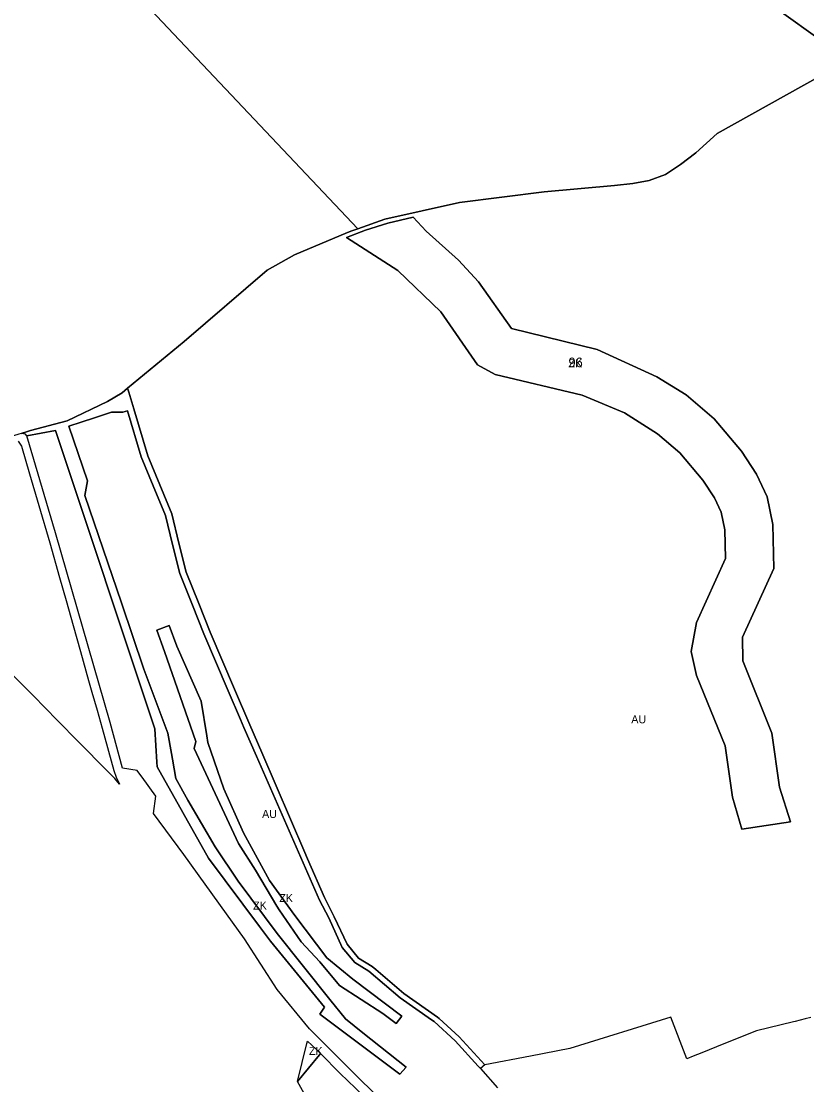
# Model space of a CAD drawing. Extents: x -535894 to -532834, y -1165802 to -1163647.
# Drawn here: x -535328 to -534838, y -1165127 to -1164462 of the extents above; entities that cross this region are included whole.
import ezdxf

# ---------------------------------------------------------------- set-up
doc = ezdxf.new("R2010")
doc.units = 0
for name, color, linetype in [('Vrstva 16', 7, 'Continuous'), ('Vrstva 17', 7, 'Continuous'), ('Vrstva 19', 7, 'Continuous'), ('Vrstva 22', 7, 'Continuous'), ('Vrstva 28', 7, 'Continuous'), ('Vrstva 61', 7, 'Continuous')]:
    doc.layers.add(name, color=color, linetype=linetype)

msp = doc.modelspace()

# ---------------------------------------------------------------- linework, layer by layer
at = {"layer": 'Vrstva 16'}
for points in [[(-535138.71, -1165009.74), (-535132.68, -1165021.61), (-535124.68, -1165038.88), (-535117.6, -1165047.48), (-535109.11, -1165052.7), (-535106.82, -1165054.65), (-535089.33, -1165069.61), (-535068.17, -1165084.42), (-535067.25, -1165085.28), (-535054.81, -1165096.75), (-535038.78, -1165114.13), (-535041.39, -1165116.45), (-535042.82, -1165114.91), (-535057.29, -1165099.23), (-535070.36, -1165087.15), (-535071.93, -1165086.06), (-535091.48, -1165072.37), (-535111.17, -1165055.54), (-535119.93, -1165050.16), (-535127.67, -1165040.76), (-535136.18, -1165022.4), (-535141.82, -1165011.33), (-535181.28, -1164921.44), (-535189.08, -1164903.47), (-535191.25, -1164898.41), (-535198.89, -1164880.55), (-535214.13, -1164844.92), (-535221.25, -1164827.04), (-535229.1, -1164807.35), (-535233.62, -1164789.13), (-535238.13, -1164771.01), (-535245.75, -1164752.59), (-535253.23, -1164734.48), (-535261.71, -1164705.66), (-535264.79, -1164706.6), (-535271.8, -1164706.52), (-535282.32, -1164710.05), (-535290.79, -1164712.78), (-535298.39, -1164715.22), (-535286.78, -1164749.373), (-535288.44, -1164758.51), (-535265.51, -1164825.67), (-535251.57, -1164867.01), (-535236.56, -1164907.02), (-535234.352, -1164919.797), (-535233.753, -1164923.265), (-535231.67, -1164935.322), (-535224.17, -1164948.96), (-535207, -1164978.01), (-535192.6, -1164999.49), (-535168.36, -1165032.09), (-535135.5, -1165073.361), (-535125.69, -1165085.45), (-535114.8, -1165094.19), (-535087.801, -1165115.542), (-535091.8, -1165120.03), (-535141.75, -1165082.45), (-535138.85, -1165078.22), (-535172.47, -1165036.89), (-535179.28, -1165027.8), (-535211.27, -1164985.05), (-535243.3, -1164928.03), (-535243.48, -1164925.188), (-535244.804, -1164904.255), (-535306.74, -1164717.91), (-535324.72, -1164721.28), (-535325.538, -1164720.285), (-535327.926, -1164719.801), (-535325.391, -1164719.016), (-535322.24, -1164718.04), (-535299.42, -1164711.94), (-535274.36, -1164699.8), (-535265.14, -1164694.54), (-535261.677, -1164691.669), (-535260.94, -1164694.17), (-535257.9, -1164704.48), (-535249.16, -1164733.82), (-535241.65, -1164751.91), (-535234.09, -1164770.13), (-535229.64, -1164788.31), (-535225.1, -1164806.57), (-535217.32, -1164826.11), (-535210.21, -1164843.9), (-535194.99, -1164879.49), (-535185.4, -1164901.91), (-535177.9, -1164919.08), (-535151, -1164981.54), (-535149.32, -1164985.4)], [(-535211.657, -1164912.919), (-535201.69, -1164941.88), (-535189.32, -1164969.17), (-535173.15, -1164998.99), (-535157.24, -1165020.97), (-535137.29, -1165047.25), (-535121.13, -1165060.64), (-535090.57, -1165083.64), (-535094.005, -1165088.367), (-535102.38, -1165082.03), (-535129.39, -1165064.5), (-535141.65, -1165049.71), (-535153.27, -1165037.38), (-535167.09, -1165017.44), (-535168.5, -1165015.08), (-535181.9, -1164992.48), (-535192.57, -1164975.97), (-535220.19, -1164916.49), (-535219.2, -1164912.17), (-535238.67, -1164856.05), (-535243.507, -1164842.754), (-535235.765, -1164839.722), (-535231.08, -1164852.62), (-535215.73, -1164887.135), (-535212.311, -1164908.777)], [(-535155.665, -1165124.565), (-535149.73, -1165100.83), (-535149.344, -1165099.292), (-535143.98, -1165104.415), (-535141.331, -1165107.067), (-535141.94, -1165107.81)]]:
    msp.add_lwpolyline(points, close=True, dxfattribs=at)
at = {"layer": 'Vrstva 17'}
msp.add_lwpolyline([(-534878.38, -1164967), (-534884.12, -1164947), (-534888.69, -1164915), (-534906.62, -1164871), (-534909.88, -1164856), (-534906.62, -1164838), (-534888.5, -1164798), (-534888.81, -1164780), (-534891.12, -1164769), (-534895.31, -1164760), (-534902.62, -1164749), (-534916.88, -1164732), (-534930.88, -1164720), (-534951.62, -1164707), (-534977.88, -1164696), (-535032.31, -1164683), (-535043.38, -1164677), (-535066.12, -1164644), (-535093, -1164618), (-535125.13, -1164597.55), (-535113.13, -1164592.91), (-535099.23, -1164588.45), (-535083.39, -1164584.89), (-535075.37, -1164593.51), (-535055.24, -1164611.61), (-535042.64, -1164625.2), (-535022.12, -1164654.4), (-534968.54, -1164667.39), (-534931.28, -1164684.5), (-534913.05, -1164695.77), (-534895.48, -1164710.83), (-534878.56, -1164731), (-534869.07, -1164745.28), (-534862.47, -1164759.46), (-534858.86, -1164776.63), (-534858.39, -1164804.23), (-534877.76, -1164847), (-534877.62, -1164861.87), (-534859.51, -1164907.1), (-534854.71, -1164940.71), (-534847.89, -1164962.32)], close=True, dxfattribs=at)
at = {"layer": 'Vrstva 19'}
msp.add_lwpolyline([(-534866.733, -1164446.894), (-534817.509, -1164482.62), (-534819.12, -1164488.91), (-534820.5, -1164491.79), (-534822.728, -1164493.033), (-534828.796, -1164496.418), (-534893.74, -1164532.65), (-534906.91, -1164544.6), (-534916.57, -1164551.88), (-534926.03, -1164558.08), (-534936.2, -1164561.96), (-534946.31, -1164563.69), (-534957.79, -1164565.07), (-535001.64, -1164568.89), (-535054.61, -1164575.73), (-535101.2, -1164586.14), (-535117.95, -1164592.03), (-535326.28, -1164371.53)], dxfattribs=at)
at = {"layer": 'Vrstva 22'}
for points in [[(-534817.509, -1164482.62), (-534866.733, -1164446.894)], [(-534835.13, -1165084.593), (-534838.685, -1165085.472), (-534845.072, -1165087.05), (-534845.969, -1165087.272), (-534869.07, -1165092.98), (-534889.43, -1165100.93), (-534903.3, -1165106.635), (-534908.615, -1165108.822), (-534912.55, -1165110.44), (-534922.682, -1165084.357), (-534985.58, -1165103.95), (-535010.28, -1165108.81), (-535038.78, -1165114.13), (-535054.81, -1165096.75), (-535067.25, -1165085.28), (-535068.17, -1165084.42), (-535089.33, -1165069.61), (-535106.82, -1165054.65), (-535109.11, -1165052.7), (-535117.6, -1165047.48), (-535124.68, -1165038.88), (-535132.68, -1165021.61), (-535138.71, -1165009.74), (-535149.32, -1164985.4), (-535151, -1164981.54), (-535177.9, -1164919.08), (-535185.4, -1164901.91), (-535194.99, -1164879.49), (-535210.21, -1164843.9), (-535217.32, -1164826.11), (-535225.1, -1164806.57), (-535229.64, -1164788.31), (-535234.09, -1164770.13), (-535241.65, -1164751.91), (-535249.16, -1164733.82), (-535257.9, -1164704.48), (-535260.94, -1164694.17), (-535261.677, -1164691.669), (-535226.37, -1164662.4), (-535174.63, -1164617.97), (-535157.57, -1164608.35), (-535124.4, -1164594.3), (-535121.76, -1164593.37), (-535117.95, -1164592.03), (-535101.2, -1164586.14), (-535054.61, -1164575.73), (-535001.64, -1164568.89), (-534957.79, -1164565.07), (-534946.31, -1164563.69), (-534936.2, -1164561.96), (-534926.03, -1164558.08), (-534916.57, -1164551.88), (-534906.91, -1164544.6), (-534893.74, -1164532.65), (-534828.796, -1164496.418)], [(-535105.854, -1165133.419), (-535115.229, -1165124.489), (-535148.121, -1165091.686), (-535168.377, -1165067.011), (-535188.741, -1165035.391), (-535199.872, -1165019.877), (-535226.518, -1164982.739), (-535245.617, -1164957.123), (-535244.088, -1164946.44), (-535252.719, -1164934.506), (-535254.681, -1164931.794), (-535255.808, -1164930.235), (-535264.937, -1164928.872), (-535272.55, -1164900.37), (-535306.74, -1164781.96), (-535324.72, -1164721.28), (-535306.74, -1164717.91), (-535244.804, -1164904.255), (-535243.48, -1164925.188), (-535243.3, -1164928.03), (-535211.27, -1164985.05), (-535179.28, -1165027.8), (-535172.47, -1165036.89), (-535138.85, -1165078.22), (-535141.75, -1165082.45), (-535091.8, -1165120.03), (-535087.801, -1165115.542), (-535114.8, -1165094.19), (-535125.69, -1165085.45), (-535135.5, -1165073.361), (-535168.36, -1165032.09), (-535192.6, -1164999.49), (-535207, -1164978.01), (-535224.17, -1164948.96), (-535231.67, -1164935.322), (-535233.753, -1164923.265), (-535234.352, -1164919.797), (-535236.56, -1164907.02), (-535251.57, -1164867.01), (-535265.51, -1164825.67), (-535288.44, -1164758.51), (-535286.78, -1164749.373), (-535298.39, -1164715.22), (-535290.79, -1164712.78), (-535282.32, -1164710.05), (-535271.8, -1164706.52), (-535264.79, -1164706.6), (-535261.71, -1164705.66), (-535253.23, -1164734.48), (-535245.75, -1164752.59), (-535238.13, -1164771.01), (-535233.62, -1164789.13), (-535229.1, -1164807.35), (-535221.25, -1164827.04), (-535214.13, -1164844.92), (-535198.89, -1164880.55), (-535191.25, -1164898.41), (-535189.08, -1164903.47), (-535181.28, -1164921.44), (-535141.82, -1165011.33), (-535136.18, -1165022.4), (-535127.67, -1165040.76), (-535119.93, -1165050.16), (-535111.17, -1165055.54), (-535091.48, -1165072.37), (-535071.93, -1165086.06), (-535070.36, -1165087.15), (-535057.29, -1165099.23), (-535042.82, -1165114.91), (-535041.39, -1165116.45), (-535030.794, -1165128.551)], [(-535330.07, -1164724.66), (-535328.05, -1164727.88), (-535322.98, -1164745.04), (-535317.16, -1164764.78), (-535310.26, -1164788.12), (-535304.15, -1164809.81), (-535300.1, -1164824.22), (-535295.73, -1164839.71), (-535291.17, -1164855.92), (-535286.04, -1164874.13), (-535284.01, -1164881.32), (-535280.81, -1164892.67), (-535277.63, -1164903.97), (-535270.21, -1164930.28), (-535268.776, -1164934.471), (-535266.73, -1164938.9), (-535269.72, -1164935.43), (-535272.25, -1164932.85), (-535294.62, -1164910.11), (-535303.11, -1164901.49), (-535315.47, -1164888.93), (-535318.27, -1164886.08), (-535333.29, -1164870.81)]]:
    msp.add_lwpolyline(points, dxfattribs=at)
for points in [[(-534854.71, -1164940.71), (-534859.51, -1164907.1), (-534877.62, -1164861.87), (-534877.76, -1164847), (-534858.39, -1164804.23), (-534858.86, -1164776.63), (-534862.47, -1164759.46), (-534869.07, -1164745.28), (-534878.56, -1164731), (-534895.48, -1164710.83), (-534913.05, -1164695.77), (-534931.28, -1164684.5), (-534968.54, -1164667.39), (-535022.12, -1164654.4), (-535042.64, -1164625.2), (-535055.24, -1164611.61), (-535075.37, -1164593.51), (-535083.39, -1164584.89), (-535099.23, -1164588.45), (-535113.13, -1164592.91), (-535125.13, -1164597.55), (-535093, -1164618), (-535066.12, -1164644), (-535043.38, -1164677), (-535032.31, -1164683), (-534977.88, -1164696), (-534951.62, -1164707), (-534930.88, -1164720), (-534916.88, -1164732), (-534902.62, -1164749), (-534895.31, -1164760), (-534891.12, -1164769), (-534888.81, -1164780), (-534888.5, -1164798), (-534906.62, -1164838), (-534909.88, -1164856), (-534906.62, -1164871), (-534888.69, -1164915), (-534884.12, -1164947), (-534878.38, -1164967), (-534847.89, -1164962.32)], [(-535102.38, -1165082.03), (-535094.005, -1165088.367), (-535090.57, -1165083.64), (-535121.13, -1165060.64), (-535137.29, -1165047.25), (-535157.24, -1165020.97), (-535173.15, -1164998.99), (-535189.32, -1164969.17), (-535201.69, -1164941.88), (-535211.657, -1164912.919), (-535212.311, -1164908.777), (-535215.73, -1164887.135), (-535231.08, -1164852.62), (-535235.765, -1164839.722), (-535243.507, -1164842.754), (-535238.67, -1164856.05), (-535219.2, -1164912.17), (-535220.19, -1164916.49), (-535192.57, -1164975.97), (-535181.9, -1164992.48), (-535168.5, -1165015.08), (-535167.09, -1165017.44), (-535153.27, -1165037.38), (-535141.65, -1165049.71), (-535129.39, -1165064.5)], [(-535141.331, -1165107.067), (-535128.931, -1165119.482), (-535119.396, -1165128.806), (-535110.216, -1165137.551), (-535101.402, -1165147.865), (-535089.002, -1165163.415), (-535098.68, -1165165.83), (-535109.532, -1165169.282), (-535113.551, -1165171.039), (-535118.727, -1165173.09), (-535119.161, -1165173.236), (-535120.442, -1165173.67), (-535124.139, -1165174.765), (-535131.907, -1165176.691), (-535136.049, -1165177.441), (-535137.699, -1165177.679), (-535139.073, -1165168.99), (-535141.761, -1165155.672), (-535144.388, -1165147.195), (-535145.543, -1165143.469), (-535148.99, -1165136.793), (-535152.58, -1165130.217), (-535155.665, -1165124.565), (-535141.94, -1165107.81)]]:
    msp.add_lwpolyline(points, close=True, dxfattribs=at)
at = {"layer": 'Vrstva 28'}
msp.add_lwpolyline([(-535326.28, -1164371.53), (-535117.95, -1164592.03), (-535121.76, -1164593.37), (-535124.4, -1164594.3), (-535157.57, -1164608.35), (-535174.63, -1164617.97), (-535226.37, -1164662.4), (-535261.677, -1164691.669), (-535265.14, -1164694.54), (-535274.36, -1164699.8), (-535299.42, -1164711.94), (-535322.24, -1164718.04), (-535325.391, -1164719.016), (-535332.273, -1164721.148), (-535337.8, -1164722.86), (-535434.81, -1164774.69), (-535538.55, -1164687.07), (-535605.04, -1164629.61), (-535608.87, -1164626.28), (-535731.43, -1164520.35), (-535750.75, -1164503.89), (-535752.85, -1164502.11), (-535502.883, -1164246.986)], dxfattribs=at)

# ---------------------------------------------------------------- texts
at = {"layer": 'Vrstva 16'}
for rotation, p in [(0, (-535167.0385, -1165012.4737)), (0, (-535183.353, -1165017.1416)), (360, (-535148.498, -1165107.9579))]:
    msp.add_text('ZK', height=5, rotation=rotation, dxfattribs=at).set_placement(p)
at = {"layer": 'Vrstva 17'}
msp.add_text('ZK', height=5, rotation=360, dxfattribs=at).set_placement((-534986.51, -1164678.4861))
at = {"layer": 'Vrstva 22'}
for rotation, p in [(360, (-534947.2935, -1164900.8677)), (359.9999999, (-535177.757, -1164959.9797))]:
    msp.add_text('AU', height=5, rotation=rotation, dxfattribs=at).set_placement(p)
at = {"layer": 'Vrstva 61'}
msp.add_text('96', height=6, rotation=0, dxfattribs=at).set_placement((-534986.51, -1164678.4861))

doc.saveas('drawing.dxf')
